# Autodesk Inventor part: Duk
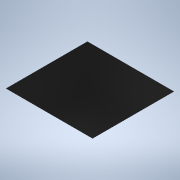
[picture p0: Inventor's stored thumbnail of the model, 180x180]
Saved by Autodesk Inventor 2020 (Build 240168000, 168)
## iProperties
Created: 2019-06
Part Number: Duk
Material: Acetal Resin, Black
Document SubType Name: Modeling
Designer: cl
Density: 1.425 g/cm^3
Appearance: Smooth - Black
Author: cl
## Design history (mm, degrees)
sketch "Sketch1"
  geometry: L1 (0, 0)-(3190, 0); L2 (3190, 0)-(3190, -3000); L3 (3190, -3000)-(0, -3000); L4 (0, -3000)-(0, 0)
  constraints: 8 end point, 2 parallel, 1 horizontal, 1 perpendicular
  dimensions: "d0" = 3190 distance of L2.end L3.end (computed from Daghöjd); "d1" = 3000 distance of L3.end L1.start (= Dagbredd)
extrude "Extrusion1" new body sketch "Sketch1" distance "d2" = 1.5; taper "d3" = 0 deg
body "Solid1"
other parameters: "Dagbredd" = 3000
